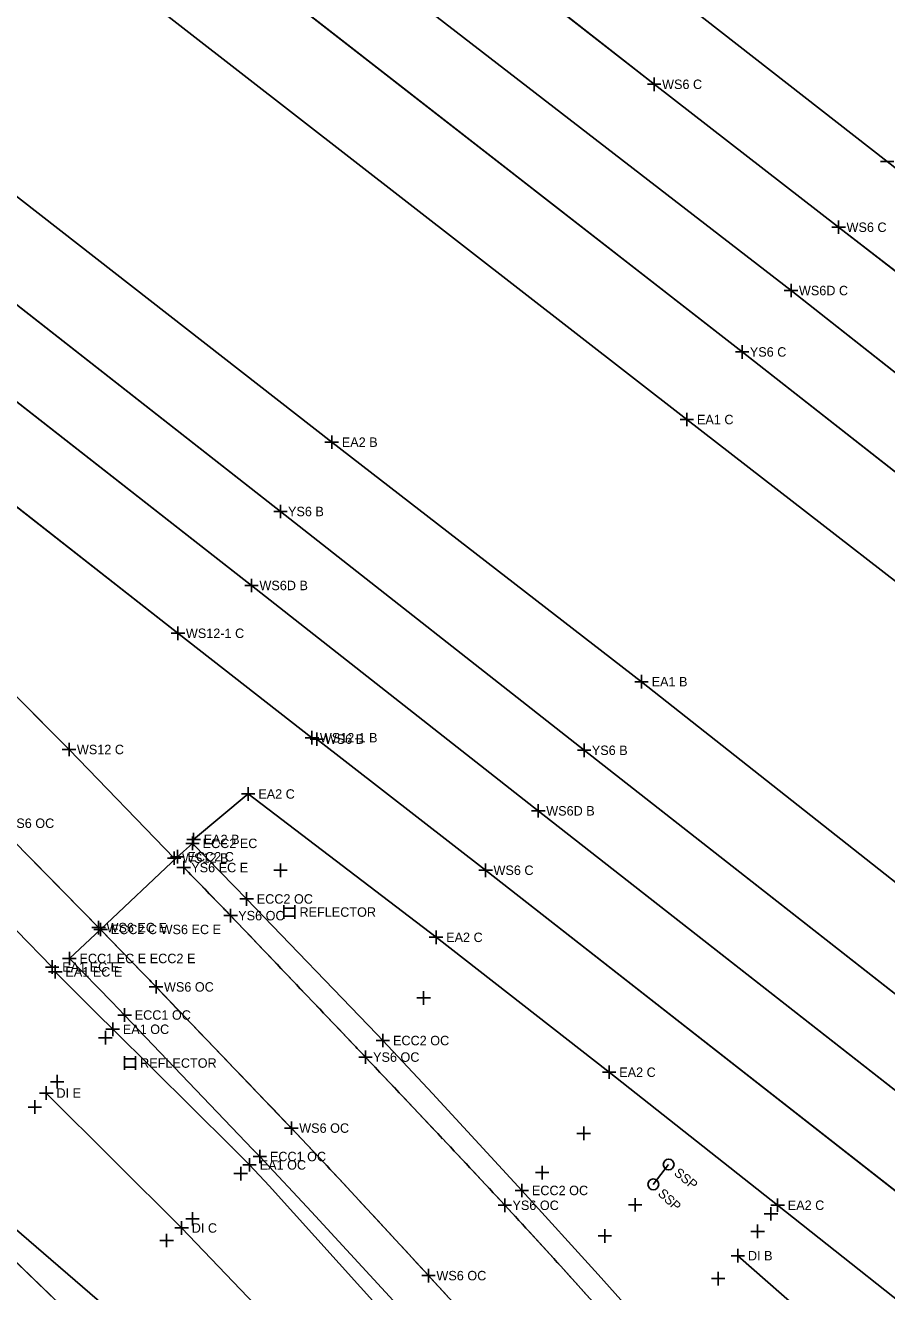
# Model space of a CAD drawing. Extents: x 1324236 to 1326110, y 459090 to 460782.
# Drawn here: x 1324624.6 to 1324752.2, y 460263.6 to 460451 of the extents above; entities that cross this region are included whole.
import ezdxf

# ---------------------------------------------------------------- set-up
doc = ezdxf.new("R2010")
doc.units = 0
for name, color, linetype in [('BD_X_Canopy', 7, 'Continuous'), ('DR_X_Ditch', 7, 'Continuous'), ('DR_X_Drive_Pipe', 7, 'Continuous'), ('DR_X_Storm_Sewer', 7, 'Continuous'), ('DT_X_Contour_Minor', 7, 'Continuous'), ('DT_X_Island', 7, 'Continuous'), ('DT_X_Terrain_Ground_Line', 7, 'Continuous'), ('DV_X_Property_Line', 7, 'Continuous'), ('E-RW-ODOT', 7, 'Continuous'), ('PM_X_Edge_Line', 7, 'Continuous'), ('PM_X_Lane_Line', 7, 'Continuous'), ('PV_X_Shoulder', 7, 'Continuous'), ('RW_X_CL', 7, 'Continuous'), ('RW_X_Esmt_SH', 7, 'Continuous')]:
    doc.layers.add(name, color=color, linetype=linetype)

msp = doc.modelspace()

# ---------------------------------------------------------------- linework, layer by layer
at = {"layer": 'BD_X_Canopy'}
for points in [[(1324899.46, 460285.8), (1324816.32, 460350.02), (1324738, 460411.76), (1324655.48, 460475.52), (1324571, 460541.76), (1324483.76, 460609.87), (1324398.74, 460676.2), (1324371.29, 460697.8)], [(1324658.11, 460368.1), (1324570.73, 460436.38), (1324490.36, 460498.76), (1324409.95, 460562.12), (1324331.06, 460623.37)], [(1324658.11, 460368.1), (1324700.58, 460334.74), (1324777.36, 460274.61), (1324857.99, 460211.28), (1324902.59, 460176.58)]]:
    msp.add_lwpolyline(points, dxfattribs=at)
at = {"layer": 'DR_X_Ditch'}
for points in [[(1324878.81, 460316.8), (1324851.22, 460338.14), (1324823.13, 460360.06), (1324797.18, 460380.62), (1324771.19, 460400.89), (1324745.05, 460421.13), (1324717.74, 460442.29), (1324690.08, 460463.98), (1324662.89, 460485.28), (1324634.89, 460507.31), (1324608, 460528.25), (1324578.82, 460551.06), (1324545.51, 460577.03), (1324519.35, 460597.5), (1324491.34, 460619.11), (1324462.72, 460641.59), (1324434.69, 460663.56), (1324406.17, 460685.88), (1324379.47, 460706.64)], [(1324891.6, 460277.31), (1324809.63, 460340.84), (1324730.77, 460402.67), (1324648.48, 460466.74), (1324563.88, 460532.79), (1324477.11, 460600.29), (1324390.8, 460667.51), (1324364.85, 460687.72)], [(1324662.39, 460379.05), (1324578.69, 460444.65), (1324497.47, 460507.91), (1324417.96, 460569.9), (1324337.82, 460632.62)], [(1324667.06, 460345.56), (1324647.22, 460361.02), (1324483.59, 460489.21), (1324464.02, 460504.01)], [(1324646.66, 460327.74), (1324631.08, 460343.82), (1324575.74, 460399.49), (1324563.15, 460412.14), (1324563.15, 460412.14), (1324559.08, 460416.13), (1324559.08, 460416.13), (1324522.78, 460450.99), (1324522.78, 460450.99), (1324519.71, 460453.9), (1324519.71, 460453.9), (1324516.77, 460456.61), (1324516.77, 460456.61), (1324481.71, 460488.51), (1324481.71, 460488.51), (1324477.34, 460492.41), (1324477.34, 460492.41), (1324464.02, 460504.01), (1324464.02, 460504.01)], [(1324536.82, 460416.88), (1324548.44, 460405.53), (1324548.44, 460405.53), (1324565.04, 460389.15), (1324565.04, 460389.15), (1324573.05, 460381.14), (1324573.05, 460381.14), (1324584.94, 460369.1), (1324584.94, 460369.1), (1324596.85, 460356.96), (1324596.85, 460356.96), (1324599.84, 460353.89), (1324599.84, 460353.89), (1324620.34, 460332.9), (1324620.34, 460332.9), (1324624.61, 460328.53), (1324624.61, 460328.53), (1324635.46, 460317.45), (1324635.46, 460317.45)], [(1324662.39, 460379.05), (1324707.37, 460343.7), (1324784.75, 460283.06), (1324865.19, 460220.08), (1324910.42, 460185.13)], [(1324667.79, 460345.35), (1324692.77, 460325.94), (1324770.4, 460265.2), (1324850.27, 460202.19), (1324895.72, 460166.83)], [(1324715.8, 460254.06), (1324703.9, 460267.33), (1324703.9, 460267.33), (1324695.63, 460276.34), (1324695.63, 460276.34), (1324686.4, 460286.21), (1324686.4, 460286.21), (1324674.99, 460298.28), (1324674.99, 460298.28), (1324673.36, 460299.99), (1324673.36, 460299.99), (1324655.01, 460319.22), (1324655.01, 460319.22), (1324653.58, 460320.7), (1324653.58, 460320.7), (1324648.06, 460326.34), (1324648.06, 460326.34)], [(1324696.37, 460252.7), (1324684.32, 460265.93), (1324684.32, 460265.93), (1324671.04, 460280.3), (1324671.04, 460280.3), (1324664.01, 460287.77), (1324664.01, 460287.77), (1324663.15, 460288.67), (1324663.15, 460288.67), (1324643.97, 460308.67), (1324643.97, 460308.67), (1324642.08, 460310.64), (1324642.08, 460310.64), (1324635.76, 460317.18), (1324635.76, 460317.18)]]:
    msp.add_lwpolyline(points, dxfattribs=at)
at = {"layer": 'DR_X_Drive_Pipe'}
for p, q in [((1324647.76, 460272.98), (1324627.72, 460292.96)), ((1324668.14, 460251.75), (1324647.76, 460272.98)), ((1324730.12, 460268.88), (1324754.93, 460247.17))]:
    msp.add_line(p, q, dxfattribs=at)
at = {"layer": 'DR_X_Storm_Sewer'}
for p, q in [((1324647.22, 460361.02), (1324483.59, 460489.21)), ((1324631.08, 460343.82), (1324575.74, 460399.49)), ((1324667.06, 460345.56), (1324647.22, 460361.02)), ((1324646.66, 460327.74), (1324631.08, 460343.82))]:
    msp.add_line(p, q, dxfattribs=at)
at = {"layer": 'DT_X_Contour_Minor'}
msp.add_line((1324717.61, 460279.44), (1324719.88, 460282.38), dxfattribs=at)
for centre in [(1324719.88, 460282.38), (1324717.61, 460279.44)]:
    msp.add_circle(centre, 0.8, dxfattribs=at)
at = {"layer": 'DT_X_Island'}
msp.add_line((1324632.66, 460258.86), (1324612.54, 460278.22), dxfattribs=at)
msp.add_lwpolyline([(1324903.24, 459851.01), (1324903.57, 459858.67), (1324900.76, 459865.01), (1324892.6, 459881.25), (1324884.84, 459894.47), (1324875.27, 459911.41), (1324865.42, 459926.97), (1324851.91, 459949.8), (1324844.34, 459963.96), (1324828.37, 459990.29), (1324813.52, 460017.04), (1324795.99, 460045.7), (1324776.37, 460074.14), (1324759.04, 460097.56), (1324741.91, 460121.91), (1324723.89, 460144.49), (1324705.48, 460167.97), (1324684.34, 460188.18), (1324670.72, 460214.69), (1324651.5, 460238.08), (1324632.66, 460258.86), (1324612.54, 460278.22)], dxfattribs=at)
at = {"layer": 'DT_X_Terrain_Ground_Line'}
for p, q in [((1324662.91, 460320.75), (1324662.91, 460318.75)), ((1324664.51, 460320.75), (1324664.51, 460318.75)), ((1324662.91, 460320.35), (1324664.51, 460320.35)), ((1324662.91, 460319.15), (1324664.51, 460319.15)), ((1324639.31, 460298.4), (1324639.31, 460296.4)), ((1324640.91, 460298.4), (1324640.91, 460296.4)), ((1324639.31, 460298), (1324640.91, 460298)), ((1324639.31, 460296.8), (1324640.91, 460296.8))]:
    msp.add_line(p, q, dxfattribs=at)
at = {"layer": 'DV_X_Property_Line'}
for p, q in [((1324751.25, 460430.86), (1324753.25, 460430.86)), ((1324721.57, 460392.66), (1324723.57, 460392.66)), ((1324722.57, 460391.66), (1324722.57, 460393.66)), ((1324669.98, 460388.31), (1324669.98, 460390.31)), ((1324668.98, 460389.31), (1324670.98, 460389.31)), ((1324715.86, 460352.85), (1324715.86, 460354.85)), ((1324714.86, 460353.85), (1324716.86, 460353.85)), ((1324657.61, 460336.23), (1324657.61, 460338.23)), ((1324656.61, 460337.23), (1324658.61, 460337.23)), ((1324648.53, 460330.5), (1324650.53, 460330.5)), ((1324649.36, 460328.92), (1324649.36, 460330.92)), ((1324649.53, 460329.5), (1324649.53, 460331.5)), ((1324647.13, 460326.94), (1324647.13, 460328.94)), ((1324648.36, 460329.92), (1324650.36, 460329.92)), ((1324646.13, 460327.94), (1324648.13, 460327.94)), ((1324657.38, 460320.69), (1324657.38, 460322.69)), ((1324656.38, 460321.69), (1324658.38, 460321.69)), ((1324634.76, 460317.18), (1324636.76, 460317.18)), ((1324635.76, 460316.18), (1324635.76, 460318.18)), ((1324685.43, 460315.01), (1324685.43, 460317.01)), ((1324684.43, 460316.01), (1324686.43, 460316.01)), ((1324631.13, 460311.88), (1324631.13, 460313.88)), ((1324627.58, 460311.61), (1324629.58, 460311.61)), ((1324628.58, 460310.61), (1324628.58, 460312.61)), ((1324629.05, 460309.9), (1324629.05, 460311.9)), ((1324630.13, 460312.88), (1324632.13, 460312.88)), ((1324628.05, 460310.9), (1324630.05, 460310.9)), ((1324638.31, 460304.51), (1324640.31, 460304.51)), ((1324639.31, 460303.51), (1324639.31, 460305.51)), ((1324636.55, 460302.4), (1324638.55, 460302.4)), ((1324637.55, 460301.4), (1324637.55, 460303.4)), ((1324676.56, 460300.73), (1324678.56, 460300.73)), ((1324677.56, 460299.73), (1324677.56, 460301.73)), ((1324711.06, 460295.04), (1324711.06, 460297.04)), ((1324710.06, 460296.04), (1324712.06, 460296.04)), ((1324657.82, 460281.32), (1324657.82, 460283.32)), ((1324658.33, 460283.56), (1324660.33, 460283.56)), ((1324659.33, 460282.56), (1324659.33, 460284.56)), ((1324656.82, 460282.32), (1324658.82, 460282.32)), ((1324698.13, 460277.54), (1324698.13, 460279.54)), ((1324697.13, 460278.54), (1324699.13, 460278.54)), ((1324735.02, 460276.35), (1324737.02, 460276.35)), ((1324736.02, 460275.35), (1324736.02, 460277.35))]:
    msp.add_line(p, q, dxfattribs=at)
at = {"layer": 'E-RW-ODOT'}
msp.add_line((1324967.69, 459977.08), (1324507.19, 460372.32), dxfattribs=at)
at = {"layer": 'PM_X_Edge_Line'}
for p, q in [((1324730.77, 460402.67), (1324648.48, 460466.74)), ((1324717.74, 460442.29), (1324690.08, 460463.98)), ((1324662.39, 460379.05), (1324578.69, 460444.65)), ((1324745.05, 460421.13), (1324717.74, 460442.29)), ((1324771.19, 460400.89), (1324745.05, 460421.13)), ((1324809.63, 460340.84), (1324730.77, 460402.67)), ((1324662.39, 460379.05), (1324707.37, 460343.7)), ((1324667.79, 460345.35), (1324692.77, 460325.94)), ((1324707.37, 460343.7), (1324784.75, 460283.06)), ((1324692.77, 460325.94), (1324770.4, 460265.2))]:
    msp.add_line(p, q, dxfattribs=at)
for centre, radius, start, end in [((1355937.92, 490966.98), 43809.11, 224.375879, 224.396167), ((1322716.97, 458430.55), 2706.13, 44.30433, 44.47151), ((1324521.4, 460191.69), 184.71, 43.6644, 44.3043), ((1239813.57, 379343.72), 117282.15, 43.6514375, 43.6644168), ((1318562.47, 454438.97), 8452.11, 44.003206, 44.064844), ((1324091.83, 459779.21), 764.98, 43.79832, 44.0032), ((1174051.09, 315903.77), 208640.82, 43.7907108, 43.7983192), ((1324000.71, 459658.29), 929.64, 43.50565, 43.65144), ((1321959.69, 457721.05), 3743.65, 43.25142, 43.50565), ((1324360.13, 459998.18), 419.76, 43.6211, 43.7907), ((1324055.66, 459708.03), 840.35, 42.92133, 43.62109), ((1322881.57, 458588.31), 2477.96, 42.93894, 43.25142), ((1322434.86, 458200.76), 3053.68, 42.55425, 42.92133), ((1324038.56, 459664.92), 897.54, 42.15786, 42.93894), ((1323293.84, 458990.64), 1902.16, 41.62133, 42.15786), ((1323122.79, 458832.33), 2119.81, 42.07053, 42.55425)]:
    msp.add_arc(centre, radius, start, end, dxfattribs=at)
at = {"layer": 'PM_X_Lane_Line'}
for p, q in [((1324738, 460411.76), (1324655.48, 460475.52)), ((1324658.11, 460368.1), (1324570.73, 460436.38)), ((1324816.32, 460350.02), (1324738, 460411.76)), ((1324658.11, 460368.1), (1324700.58, 460334.74)), ((1324700.58, 460334.74), (1324777.36, 460274.61))]:
    msp.add_line(p, q, dxfattribs=at)
at = {"layer": 'PV_X_Shoulder'}
for points in [[(1324884.45, 460266.49), (1324856.61, 460288.28), (1324829.47, 460309.8), (1324801.93, 460331.35), (1324773.75, 460352.98), (1324722.57, 460392.66), (1324640.21, 460456.72), (1324556.83, 460521.94), (1324468.66, 460590.9), (1324383.42, 460657.59), (1324356.31, 460678.35)], [(1324669.98, 460389.31), (1324586.32, 460454.48), (1324504.97, 460517.77), (1324425.87, 460579.19), (1324344.79, 460642.38)], [(1324886.1, 460326.42), (1324858.75, 460347.83), (1324830.89, 460369.39), (1324804.09, 460390.5), (1324778.12, 460410.62), (1324752.25, 460430.86), (1324725.08, 460452.05), (1324697.48, 460473.35), (1324670.11, 460494.77), (1324642.41, 460516.54), (1324614.82, 460537.84), (1324586.12, 460559.97), (1324553.47, 460586.1), (1324557.53, 460592.81)], [(1324541.56, 460398.57), (1324559.1, 460381.45), (1324559.1, 460381.45), (1324565.85, 460374.76), (1324565.85, 460374.76), (1324575.16, 460365.41), (1324575.16, 460365.41), (1324589.63, 460350.84), (1324589.63, 460350.84), (1324593.4, 460347.06), (1324593.4, 460347.06), (1324613.89, 460326.55), (1324613.89, 460326.55), (1324617.95, 460322.45), (1324617.95, 460322.45), (1324628.58, 460311.61), (1324628.58, 460311.61)], [(1324669.98, 460389.31), (1324715.86, 460353.85), (1324792.73, 460293.17), (1324872.96, 460231.13), (1324952.76, 460169.1), (1324978.52, 460148.79), (1325005.25, 460128.1), (1325032.05, 460107.12), (1325058.52, 460086.64), (1325084, 460067.05), (1325111.27, 460046.59)], [(1324649.53, 460330.5), (1324657.61, 460337.23), (1324685.43, 460316.01), (1324711.06, 460296.04), (1324736.02, 460276.35), (1324762.82, 460255.12), (1324789.54, 460234.24), (1324816.21, 460213.47), (1324842.97, 460192.59), (1324868.9, 460172.35), (1324896.06, 460152.06), (1324922.98, 460130.99), (1324949.48, 460111.07), (1324976.29, 460090.49), (1325004.33, 460071.45), (1325031.27, 460052.08), (1325058.13, 460031.85), (1325085.59, 460011.5)], [(1324718.3, 460256.23), (1324709.44, 460266.1), (1324709.44, 460266.1), (1324698.13, 460278.54), (1324698.13, 460278.54), (1324684.93, 460292.87), (1324684.93, 460292.87), (1324677.56, 460300.73), (1324677.56, 460300.73), (1324676.65, 460301.68), (1324676.65, 460301.68), (1324657.38, 460321.69), (1324657.38, 460321.69), (1324655.55, 460323.58), (1324655.55, 460323.58), (1324649.36, 460329.92), (1324649.36, 460329.92), (1324647.13, 460327.94), (1324635.76, 460317.18), (1324631.13, 460312.88)], [(1324679.69, 460261.62), (1324667.01, 460275.35), (1324667.01, 460275.35), (1324659.33, 460283.56), (1324659.33, 460283.56), (1324658.32, 460284.62), (1324658.32, 460284.62), (1324639.31, 460304.51), (1324639.31, 460304.51), (1324637.44, 460306.44), (1324637.44, 460306.44), (1324631.13, 460312.88), (1324631.13, 460312.88)], [(1324677.83, 460260.21), (1324660.71, 460279.23), (1324660.71, 460279.23), (1324657.82, 460282.32), (1324657.82, 460282.32), (1324655.2, 460284.96), (1324655.2, 460284.96), (1324637.55, 460302.4), (1324637.55, 460302.4), (1324635.42, 460304.53), (1324635.42, 460304.53), (1324629.05, 460310.9), (1324629.05, 460310.9)]]:
    msp.add_lwpolyline(points, dxfattribs=at)
at = {"layer": 'RW_X_CL'}
for p, q in [((1324717.74, 460441.29), (1324717.74, 460443.29)), ((1324716.74, 460442.29), (1324718.74, 460442.29)), ((1324745.05, 460420.13), (1324745.05, 460422.13)), ((1324744.05, 460421.13), (1324746.05, 460421.13)), ((1324738, 460410.76), (1324738, 460412.76)), ((1324737, 460411.76), (1324739, 460411.76)), ((1324730.77, 460401.67), (1324730.77, 460403.67)), ((1324729.77, 460402.67), (1324731.77, 460402.67)), ((1324661.39, 460379.05), (1324663.39, 460379.05)), ((1324662.39, 460378.05), (1324662.39, 460380.05)), ((1324657.11, 460368.1), (1324659.11, 460368.1)), ((1324658.11, 460367.1), (1324658.11, 460369.1)), ((1324647.22, 460360.02), (1324647.22, 460362.02)), ((1324646.22, 460361.02), (1324648.23, 460361.02)), ((1324666.06, 460345.56), (1324668.06, 460345.56)), ((1324666.79, 460345.35), (1324668.79, 460345.35)), ((1324667.06, 460344.56), (1324667.06, 460346.56)), ((1324667.79, 460344.35), (1324667.79, 460346.35)), ((1324630.08, 460343.82), (1324632.08, 460343.82)), ((1324631.08, 460342.82), (1324631.08, 460344.82)), ((1324706.37, 460343.7), (1324708.37, 460343.7)), ((1324707.37, 460342.7), (1324707.37, 460344.7)), ((1324700.58, 460333.74), (1324700.58, 460335.74)), ((1324699.58, 460334.74), (1324701.58, 460334.74)), ((1324646.66, 460326.74), (1324646.66, 460328.74)), ((1324645.66, 460327.74), (1324647.66, 460327.74)), ((1324647.06, 460326.34), (1324649.06, 460326.34)), ((1324648.06, 460325.34), (1324648.06, 460327.34)), ((1324662.39, 460324.93), (1324662.39, 460326.93)), ((1324692.77, 460324.94), (1324692.77, 460326.94)), ((1324661.39, 460325.93), (1324663.39, 460325.93)), ((1324691.77, 460325.94), (1324693.77, 460325.94)), ((1324654.01, 460319.22), (1324656.01, 460319.22)), ((1324655.01, 460318.22), (1324655.01, 460320.22)), ((1324634.46, 460317.45), (1324636.46, 460317.45)), ((1324635.46, 460316.45), (1324635.46, 460318.45)), ((1324643.97, 460307.67), (1324643.97, 460309.67)), ((1324642.97, 460308.67), (1324644.97, 460308.67)), ((1324683.6, 460306.03), (1324683.6, 460308.03)), ((1324682.6, 460307.03), (1324684.6, 460307.03)), ((1324636.46, 460300.15), (1324636.46, 460302.15)), ((1324635.46, 460301.15), (1324637.46, 460301.15)), ((1324673.99, 460298.28), (1324675.99, 460298.28)), ((1324674.99, 460297.28), (1324674.99, 460299.28)), ((1324628.33, 460294.62), (1324630.33, 460294.62)), ((1324629.33, 460293.62), (1324629.33, 460295.63)), ((1324625.02, 460290.89), (1324627.02, 460290.89)), ((1324626.02, 460289.89), (1324626.02, 460291.89)), ((1324663.01, 460287.77), (1324665.01, 460287.77)), ((1324664.01, 460286.77), (1324664.01, 460288.77)), ((1324706.3, 460286.99), (1324708.3, 460286.99)), ((1324707.3, 460285.99), (1324707.3, 460287.99)), ((1324656.51, 460280.03), (1324656.51, 460282.03)), ((1324701.14, 460280.18), (1324701.14, 460282.18)), ((1324655.51, 460281.03), (1324657.51, 460281.03)), ((1324700.14, 460281.18), (1324702.14, 460281.18)), ((1324694.63, 460276.34), (1324696.63, 460276.34)), ((1324695.63, 460275.34), (1324695.63, 460277.34)), ((1324713.92, 460276.42), (1324715.92, 460276.42)), ((1324714.92, 460275.42), (1324714.92, 460277.42)), ((1324735.03, 460274.07), (1324735.03, 460276.07)), ((1324648.37, 460274.33), (1324650.37, 460274.33)), ((1324649.37, 460273.33), (1324649.37, 460275.33)), ((1324734.03, 460275.07), (1324736.03, 460275.07)), ((1324645.54, 460270.12), (1324645.54, 460272.12)), ((1324710.43, 460270.8), (1324710.43, 460272.8)), ((1324732.05, 460272.48), (1324734.05, 460272.48)), ((1324733.05, 460271.48), (1324733.05, 460273.48)), ((1324644.54, 460271.12), (1324646.54, 460271.12)), ((1324709.43, 460271.8), (1324711.43, 460271.8)), ((1324684.32, 460264.93), (1324684.32, 460266.93)), ((1324727.22, 460264.48), (1324727.22, 460266.48)), ((1324683.32, 460265.93), (1324685.32, 460265.93)), ((1324726.22, 460265.48), (1324728.21, 460265.48))]:
    msp.add_line(p, q, dxfattribs=at)
at = {"layer": 'RW_X_Esmt_SH'}
for p, q in [((1324626.72, 460292.96), (1324628.72, 460292.96)), ((1324627.72, 460291.96), (1324627.72, 460293.96)), ((1324647.76, 460271.98), (1324647.76, 460273.98)), ((1324646.76, 460272.98), (1324648.76, 460272.98)), ((1324729.12, 460268.88), (1324731.12, 460268.88)), ((1324730.12, 460267.88), (1324730.12, 460269.88))]:
    msp.add_line(p, q, dxfattribs=at)

# ---------------------------------------------------------------- texts
at = {"layer": 'DT_X_Contour_Minor'}
for rotation, p in [(320.6942, (1324720.56, 460280.93)), (316.6676, (1324718.18, 460277.94))]:
    msp.add_text('SSP', height=1.4, rotation=rotation, dxfattribs=at).set_placement(p)
at = {"layer": 'DV_X_Property_Line'}
for s, p in [('EA1 C', (1324724.07, 460391.96)), ('EA2 B', (1324671.48, 460388.61)), ('EA1 B', (1324717.36, 460353.15)), ('EA2 C', (1324659.11, 460336.53)), ('ECC2 EC', (1324650.86, 460329.22)), ('EA2 B', (1324651.03, 460329.8)), ('ECC2 C', (1324648.63, 460327.24)), ('ECC2 OC', (1324658.88, 460320.99)), ('ECC2 C WS6 EC E', (1324637.26, 460316.48)), ('EA2 C', (1324686.93, 460315.31)), ('ECC1 EC E ECC2 E', (1324632.63, 460312.18)), ('EA1 EC E', (1324630.08, 460310.91)), ('EA1 EC E', (1324630.55, 460310.2)), ('ECC1 OC', (1324640.81, 460303.81)), ('EA1 OC', (1324639.05, 460301.7)), ('ECC2 OC', (1324679.06, 460300.03)), ('EA2 C', (1324712.56, 460295.34)), ('ECC1 OC', (1324660.83, 460282.86)), ('EA1 OC', (1324659.32, 460281.62)), ('ECC2 OC', (1324699.63, 460277.84)), ('EA2 C', (1324737.52, 460275.65))]:
    msp.add_text(s, height=1.4, dxfattribs=at).set_placement(p)
at = {"layer": 'RW_X_CL'}
for s, p in [('WS6 C', (1324718.91, 460441.59)), ('WS6 C', (1324746.22, 460420.43)), ('WS6D C', (1324739.17, 460411.06)), ('YS6 C', (1324731.9, 460401.97)), ('YS6 B', (1324663.51, 460378.35)), ('WS6D B', (1324659.28, 460367.4)), ('WS12-1 C', (1324648.39, 460360.32)), ('WS12-1 B', (1324668.23, 460344.86)), ('WS6 B', (1324668.95, 460344.65)), ('WS12 C', (1324632.25, 460343.12)), ('YS6 B', (1324708.5, 460343)), ('WS6D B', (1324701.75, 460334.04)), ('WS6 OC', (1324621.51, 460332.2)), ('WS12 B', (1324647.83, 460327.04)), ('YS6 EC E', (1324649.18, 460325.64)), ('WS6 C', (1324693.94, 460325.24)), ('YS6 OC', (1324656.14, 460318.52)), ('WS6 EC E', (1324636.63, 460316.75)), ('WS6 OC', (1324645.14, 460307.97)), ('YS6 OC', (1324676.11, 460297.58)), ('WS6 OC', (1324665.17, 460287.07)), ('YS6 OC', (1324696.75, 460275.64)), ('WS6 OC', (1324685.49, 460265.23))]:
    msp.add_text(s, height=1.4, dxfattribs=at).set_placement(p)
at = {"layer": 'RW_X_Esmt_SH'}
for s, p in [('REFLECTOR', (1324665.21, 460319.05)), ('REFLECTOR', (1324641.61, 460296.7)), ('DI E', (1324629.22, 460292.26)), ('DI C', (1324649.26, 460272.28)), ('DI B', (1324731.62, 460268.18))]:
    msp.add_text(s, height=1.4, dxfattribs=at).set_placement(p)

doc.saveas('drawing.dxf')
